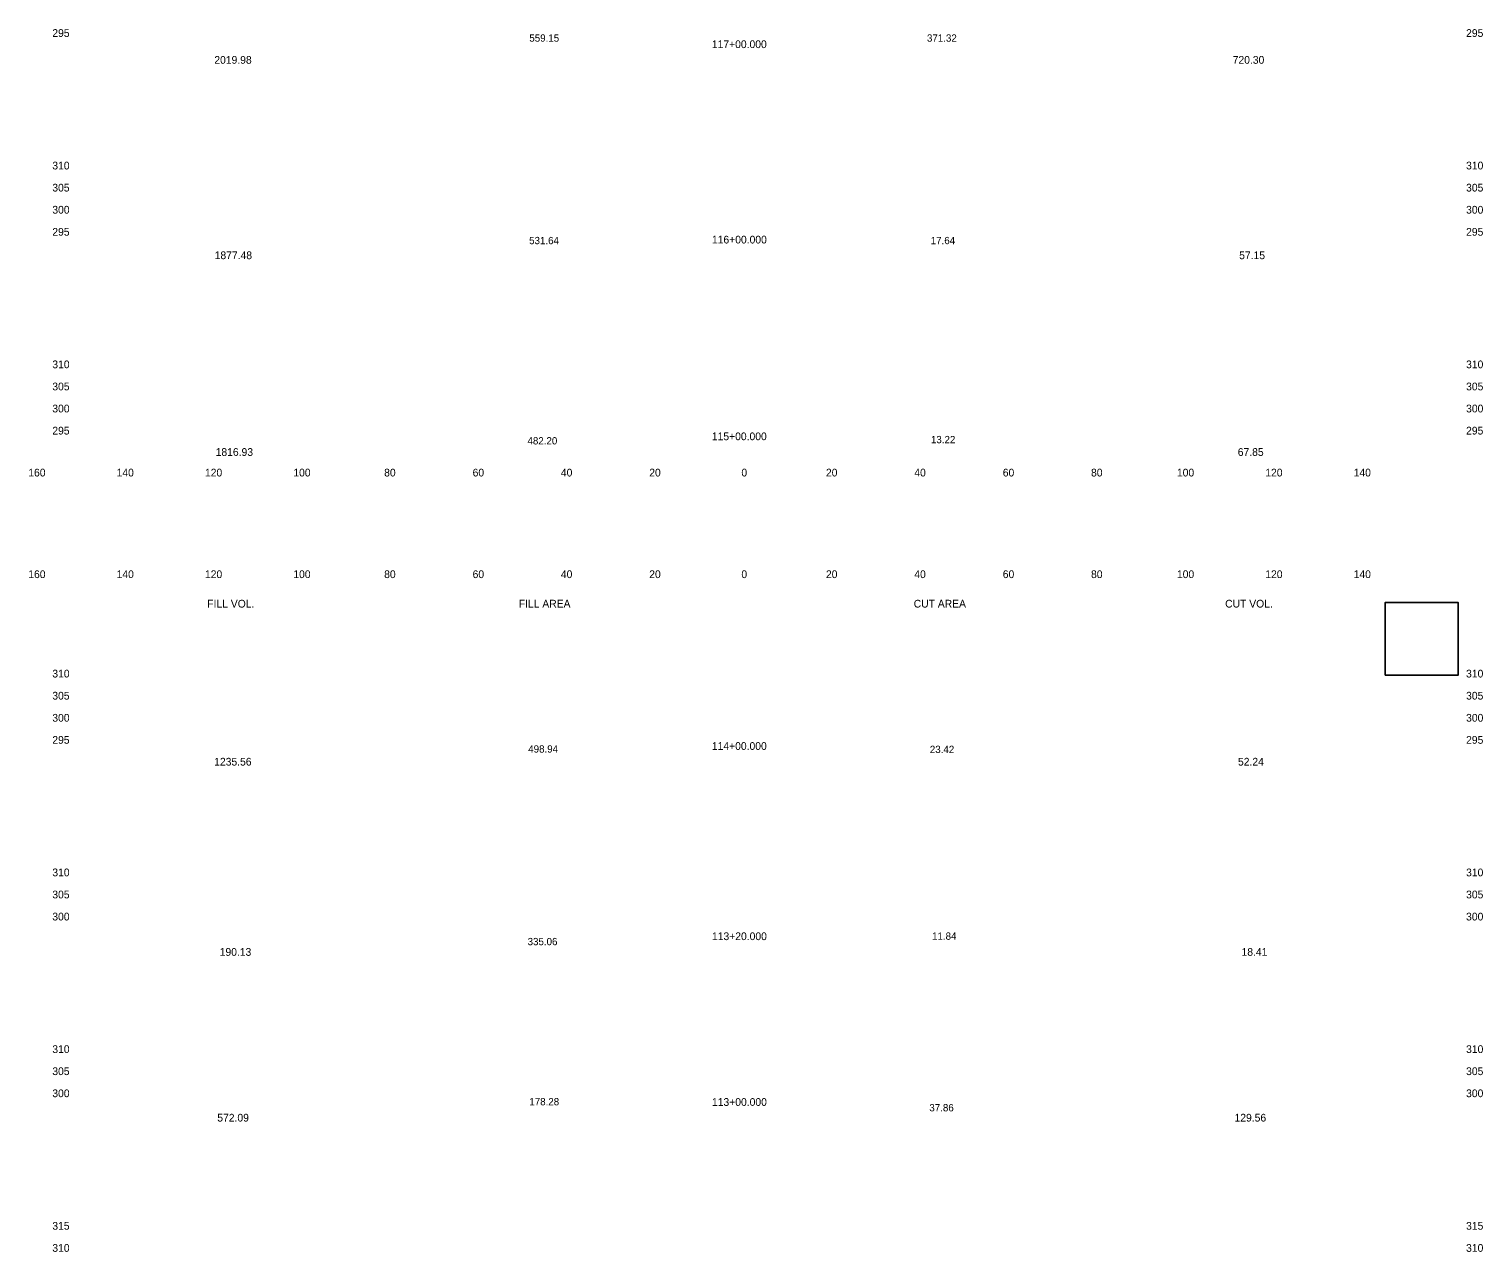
# Model space of a CAD drawing. Extents: x 21477 to 21806, y 6470 to 11049.
# Drawn here: x 21477.1 to 21806.1, y 7904.8 to 8181.6 of the extents above; entities that cross this region are included whole.
import ezdxf

# ---------------------------------------------------------------- set-up
doc = ezdxf.new("R2010")
doc.units = 0
for name, color, linetype in [('SHEET_CONSULTANT_STAMP', 7, 'Continuous'), ('XS_SHEET_EW_TX_AREA', 7, 'Continuous'), ('XS_SHEET_EW_TX_VOLUME', 7, 'Continuous'), ('XS_SHEET_LABELS_ELEVATION', 7, 'Continuous'), ('XS_SHEET_LABELS_OFFSET', 7, 'Continuous'), ('XS_SHEET_LABELS_STATION', 7, 'Continuous'), ('XS_SHEET_TX', 7, 'Continuous')]:
    doc.layers.add(name, color=color, linetype=linetype)

msp = doc.modelspace()

# ---------------------------------------------------------------- linework, layer by layer
at = {"layer": 'SHEET_CONSULTANT_STAMP'}
msp.add_lwpolyline([(21784.04, 8035.34), (21800.54, 8035.34), (21800.54, 8051.84), (21784.04, 8051.84)], close=True, dxfattribs=at)

# ---------------------------------------------------------------- texts
at = {"layer": 'XS_SHEET_EW_TX_AREA'}
for s, p in [(' 559.15 ', (21589.7, 8178.76)), (' 371.32 ', (21679.7, 8178.76)), (' 531.64 ', (21589.65, 8132.92)), (' 17.64 ', (21680.55, 8132.92)), (' 482.20 ', (21589.28, 8087.59)), (' 13.22 ', (21680.6, 8087.87)), (' 498.94 ', (21589.45, 8017.84)), (' 23.42 ', (21680.35, 8017.74)), (' 11.84 ', (21680.85, 7975.47)), (' 335.06 ', (21589.31, 7974.24)), (' 178.28 ', (21589.7, 7938)), (' 37.86 ', (21680.24, 7936.63))]:
    msp.add_text(s, height=1.65, dxfattribs=at).set_placement(p)
at = {"layer": 'XS_SHEET_EW_TX_VOLUME'}
for s, p in [(' 2019.98 ', (21518.36, 8173.76)), (' 720.30 ', (21748.86, 8173.76)), (' 1877.48 ', (21518.44, 8129.53)), (' 57.15 ', (21750.33, 8129.53)), (' 1816.93 ', (21518.66, 8085)), (' 67.85 ', (21750.01, 8085)), (' 1235.56 ', (21518.33, 8014.9)), (' 52.24 ', (21750.06, 8014.9)), (' 190.13 ', (21519.57, 7971.84)), (' 18.41 ', (21750.86, 7971.84)), (' 572.09 ', (21519.03, 7934.32)), (' 129.56 ', (21749.28, 7934.32))]:
    msp.add_text(s, height=1.75, dxfattribs=at).set_placement(p)
at = {"layer": 'XS_SHEET_LABELS_ELEVATION'}
for s, p in [('  295  ', (21481.04, 8179.84)), ('  295  ', (21801.04, 8179.84)), ('  310  ', (21481.04, 8149.84)), ('  310  ', (21801.04, 8149.84)), ('  305  ', (21481.04, 8144.84)), ('  305  ', (21801.04, 8144.84)), ('  300  ', (21481.04, 8139.84)), ('  300  ', (21801.04, 8139.84)), ('  295  ', (21481.04, 8134.84)), ('  295  ', (21801.04, 8134.84)), ('  310  ', (21481.04, 8104.84)), ('  310  ', (21801.04, 8104.84)), ('  305  ', (21481.04, 8099.84)), ('  305  ', (21801.04, 8099.84)), ('  300  ', (21481.04, 8094.84)), ('  300  ', (21801.04, 8094.84)), ('  295  ', (21481.04, 8089.84)), ('  295  ', (21801.04, 8089.84)), ('  310  ', (21481.04, 8034.84)), ('  310  ', (21801.04, 8034.84)), ('  305  ', (21481.04, 8029.84)), ('  305  ', (21801.04, 8029.84)), ('  300  ', (21481.04, 8024.84)), ('  300  ', (21801.04, 8024.84)), ('  295  ', (21481.04, 8019.84)), ('  295  ', (21801.04, 8019.84)), ('  310  ', (21481.04, 7989.84)), ('  310  ', (21801.04, 7989.84)), ('  305  ', (21481.04, 7984.84)), ('  305  ', (21801.04, 7984.84)), ('  300  ', (21481.04, 7979.84)), ('  300  ', (21801.04, 7979.84)), ('  310  ', (21481.04, 7949.84)), ('  310  ', (21801.04, 7949.84)), ('  305  ', (21481.04, 7944.84)), ('  305  ', (21801.04, 7944.84)), ('  300  ', (21481.04, 7939.84)), ('  300  ', (21801.04, 7939.84)), ('  315  ', (21481.04, 7909.84)), ('  315  ', (21801.04, 7909.84)), ('  310  ', (21481.04, 7904.84)), ('  310  ', (21801.04, 7904.84))]:
    msp.add_text(s, height=1.75, dxfattribs=at).set_placement(p)
at = {"layer": 'XS_SHEET_LABELS_OFFSET'}
for s, p in [('  160  ', (21475.6, 8080.34)), ('  140  ', (21495.59, 8080.34)), ('  120  ', (21515.59, 8080.34)), ('  100  ', (21535.59, 8080.34)), ('  80  ', (21556.15, 8080.34)), ('  60  ', (21576.17, 8080.34)), ('  40  ', (21596.15, 8080.34)), ('  20  ', (21616.15, 8080.34)), ('  0  ', (21637.01, 8080.34)), ('  0  ', (21637.01, 8080.34)), ('  20  ', (21656.15, 8080.34)), ('  40  ', (21676.15, 8080.34)), ('  60  ', (21696.17, 8080.34)), ('  80  ', (21716.15, 8080.34)), ('  100  ', (21735.59, 8080.34)), ('  120  ', (21755.59, 8080.34)), ('  140  ', (21775.59, 8080.34)), ('  160  ', (21475.6, 8057.34)), ('  140  ', (21495.59, 8057.34)), ('  120  ', (21515.59, 8057.34)), ('  100  ', (21535.59, 8057.34)), ('  80  ', (21556.15, 8057.34)), ('  60  ', (21576.17, 8057.34)), ('  40  ', (21596.15, 8057.34)), ('  20  ', (21616.15, 8057.34)), ('  0  ', (21637.01, 8057.34)), ('  0  ', (21637.01, 8057.34)), ('  20  ', (21656.15, 8057.34)), ('  40  ', (21676.15, 8057.34)), ('  60  ', (21696.17, 8057.34)), ('  80  ', (21716.15, 8057.34)), ('  100  ', (21735.59, 8057.34)), ('  120  ', (21755.59, 8057.34)), ('  140  ', (21775.59, 8057.34))]:
    msp.add_text(s, height=1.75, dxfattribs=at).set_placement(p)
at = {"layer": 'XS_SHEET_LABELS_STATION'}
for s, p in [('  117+00.000  ', (21630.32, 8177.31)), ('  116+00.000  ', (21630.34, 8133.08)), ('  115+00.000  ', (21630.32, 8088.55)), ('  114+00.000  ', (21630.32, 8018.45)), ('  113+20.000  ', (21630.35, 7975.39)), ('  113+00.000  ', (21630.35, 7937.87))]:
    msp.add_text(s, height=1.75, dxfattribs=at).set_placement(p)
at = {"layer": 'XS_SHEET_TX'}
for s, p in [('FILL VOL.', (21517.41, 8050.67)), ('FILL AREA', (21587.92, 8050.67)), ('CUT AREA', (21677.31, 8050.67)), ('CUT VOL.', (21747.8, 8050.67))]:
    msp.add_text(s, height=1.75, dxfattribs=at).set_placement(p)

doc.saveas('drawing.dxf')
